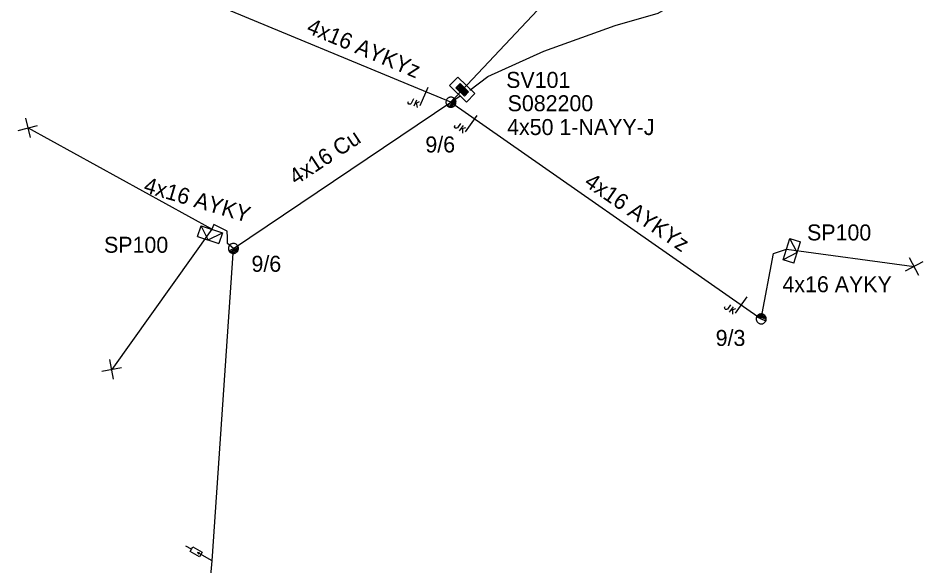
# Model space of a CAD drawing. Extents: x -788458 to -786145, y -1154772 to -1152372.
# Drawn here: x -786965.6 to -786909, y -1154604 to -1154569.7 of the extents above; entities that cross this region are included whole.
import ezdxf

# ---------------------------------------------------------------- set-up
doc = ezdxf.new("R2010")
doc.units = 0
for name, color, linetype in [('Vrstva 1', 7, 'Continuous'), ('Vrstva 12', 7, 'Continuous'), ('Vrstva 13', 7, 'Continuous'), ('Vrstva 15', 7, 'Continuous'), ('Vrstva 16', 7, 'Continuous'), ('Vrstva 18', 7, 'Continuous'), ('Vrstva 2', 7, 'Continuous'), ('Vrstva 28', 7, 'Continuous'), ('Vrstva 29', 7, 'Continuous'), ('Vrstva 30', 7, 'Continuous'), ('Vrstva 31', 7, 'Continuous'), ('Vrstva 33', 7, 'Continuous'), ('Vrstva 34', 7, 'Continuous'), ('Vrstva 5', 7, 'Continuous'), ('Vrstva 52', 7, 'Continuous'), ('Vrstva 54', 7, 'Continuous'), ('Vrstva 55', 7, 'Continuous'), ('Vrstva 59', 7, 'Continuous'), ('Vrstva 6', 7, 'Continuous'), ('Vrstva 8', 7, 'Continuous'), ('Vrstva 9', 7, 'Continuous')]:
    doc.layers.add(name, color=color, linetype=linetype)

# ---------------------------------------------------------------- blocks, each defined once
blk = doc.blocks.new('NN440')
at = {"layer": 'Vrstva 2'}
for points in [[(0.63, 0), (0.63, 0.06), (0.62, 0.13), (0.6, 0.19), (0.58, 0.25), (0.55, 0.31), (0.51, 0.37), (0.47, 0.42), (0.42, 0.46), (0.37, 0.51), (0.32, 0.54), (0.26, 0.57), (0.2, 0.59), (0.13, 0.61), (0.07, 0.62), (0, 0.63), (-0.06, 0.62), (-0.13, 0.61), (-0.19, 0.59), (-0.26, 0.57), (-0.31, 0.54), (-0.37, 0.51), (-0.42, 0.46), (-0.47, 0.42), (-0.51, 0.37), (-0.54, 0.31), (-0.57, 0.25), (-0.6, 0.19), (-0.62, 0.13), (-0.63, 0.06), (-0.63, 0), (-0.63, -0.07), (-0.62, -0.14), (-0.6, -0.2), (-0.57, -0.26), (-0.54, -0.32), (-0.51, -0.37), (-0.47, -0.43), (-0.42, -0.47), (-0.37, -0.51), (-0.31, -0.55), (-0.26, -0.58), (-0.19, -0.6), (-0.13, -0.62), (-0.06, -0.63), (0, -0.63), (0.07, -0.63), (0.13, -0.62), (0.2, -0.6), (0.26, -0.58), (0.32, -0.55), (0.37, -0.51), (0.42, -0.47), (0.47, -0.43), (0.51, -0.37), (0.55, -0.32), (0.58, -0.26), (0.6, -0.2), (0.62, -0.14), (0.63, -0.07), (0.63, 0)], [(-0.63, 0), (0.63, 0)], [(-0.6, -0.18), (0.57, -0.18)], [(-0.51, -0.32), (0.5, -0.32)], [(-0.37, -0.47), (0.35, -0.47)]]:
    blk.add_lwpolyline(points, dxfattribs=at)
blk = doc.blocks.new('NN840')
at = {"layer": 'Vrstva 15'}
for points in [[(0.003, 0.619), (0.003, -0.631)], [(-0.538, -0.385), (-0.538, -0.71)], [(-0.332, -0.385), (-0.332, -0.798)], [(-0.332, -0.641), (-0.125, -0.385)], [(-0.263, -0.557), (-0.091, -0.798)], [(-0.745, -0.71), (-0.745, -0.66)], [(-0.73, -0.764), (-0.745, -0.71)], [(-0.657, -0.798), (-0.73, -0.764)], [(-0.627, -0.798), (-0.657, -0.798)], [(-0.558, -0.764), (-0.627, -0.798)], [(-0.538, -0.71), (-0.558, -0.764)]]:
    blk.add_lwpolyline(points, dxfattribs=at)
blk = doc.blocks.new('NN800')
at = {"layer": 'Vrstva 1'}
for points in [[(-0.442, 0.442), (0.442, -0.442)], [(-0.442, -0.442), (0.442, 0.442)]]:
    blk.add_lwpolyline(points, dxfattribs=at)
blk = doc.blocks.new('NN820')
at = {"layer": 'Vrstva 13'}
for points in [[(-0.003, 0.004), (-0.003, -1.049)], [(-0.165, -0.813), (0.165, -0.813)], [(-0.165, -1.473), (-0.165, -0.813)], [(-0.003, -1.049), (-0.062, -0.926)], [(-0.003, -1.049), (0.057, -0.926)], [(0.165, -0.813), (0.165, -1.473)], [(0.165, -1.473), (-0.165, -1.473)], [(-0.003, -1.473), (-0.003, -1.871)]]:
    blk.add_lwpolyline(points, dxfattribs=at)
blk = doc.blocks.new('NN620')
at = {"layer": 'Vrstva 8'}
for points in [[(0.752, 0.004), (-0.748, 0.004)], [(-0.748, 0.004), (-0.748, -0.746)], [(0.752, -0.746), (0.752, 0.004)], [(0.368, -0.18), (-0.376, -0.18)], [(-0.376, -0.18), (-0.376, -0.558)], [(-0.376, -0.558), (0.368, -0.558)], [(0.321, -0.227), (-0.329, -0.227)], [(-0.329, -0.227), (-0.329, -0.51)], [(-0.329, -0.51), (0.321, -0.51)], [(0.274, -0.274), (-0.281, -0.274)], [(-0.281, -0.274), (-0.281, -0.463)], [(-0.281, -0.463), (0.274, -0.463)], [(0.227, -0.321), (-0.234, -0.321)], [(-0.234, -0.321), (-0.234, -0.416)], [(-0.234, -0.416), (0.227, -0.416)], [(-0.193, -0.369), (0.185, -0.369)], [(0.227, -0.416), (0.227, -0.321)], [(0.274, -0.463), (0.274, -0.274)], [(0.321, -0.51), (0.321, -0.227)], [(0.368, -0.558), (0.368, -0.18)], [(-0.748, -0.746), (0.752, -0.746)]]:
    blk.add_lwpolyline(points, dxfattribs=at)
blk = doc.blocks.new('NN630')
at = {"layer": 'Vrstva 9'}
for points in [[(-0.003, -0.7), (-0.703, 0)], [(-0.703, -0.7), (-0.703, 0), (0.697, 0), (0.697, -0.7)], [(-0.003, -0.7), (0.697, 0)], [(-0.703, -0.7), (0.697, -0.7)]]:
    blk.add_lwpolyline(points, dxfattribs=at)

msp = doc.modelspace()

# ---------------------------------------------------------------- linework, layer by layer
at = {"layer": 'Vrstva 1'}
for points in [[(-786938.55, -1154574.98), (-786925.01, -1154560.56)], [(-786953.694, -1154605.954), (-786953.49, -1154603.668), (-786952.16, -1154584.13), (-786938.55, -1154574.98)]]:
    msp.add_lwpolyline(points, dxfattribs=at)
at = {"layer": 'Vrstva 5'}
for points in [[(-786937.378, -1154574.228), (-786936.24, -1154573.37), (-786932.73, -1154571.78), (-786928.27, -1154570.19), (-786925.58, -1154569.4), (-786924.47, -1154568.76), (-786923.28, -1154567.46), (-786920.52, -1154565.96), (-786919.41, -1154565.46), (-786917.49, -1154564.45), (-786914.82, -1154562.68), (-786913.58, -1154558.8), (-786913.54, -1154557.37), (-786910.93, -1154557.77), (-786910.13, -1154557.99)], [(-786938.55, -1154574.98), (-786937.979, -1154574.587)]]:
    msp.add_lwpolyline(points, dxfattribs=at)
at = {"layer": 'Vrstva 52'}
for points in [[(-786952.16, -1154584.13), (-786952.52, -1154583.82), (-786952.53, -1154583.453), (-786952.54, -1154583.05), (-786953.38, -1154582.63), (-786953.51, -1154582.93)], [(-786919.14, -1154588.54), (-786918.37, -1154584.44), (-786917.56, -1154584.17)]]:
    msp.add_lwpolyline(points, dxfattribs=at)
at = {"layer": 'Vrstva 54'}
for points in [[(-786938.55, -1154574.98), (-786954.96, -1154568.15), (-786954.91, -1154567.81)], [(-786938.55, -1154574.98), (-786919.14, -1154588.54)]]:
    msp.add_lwpolyline(points, dxfattribs=at)
at = {"layer": 'Vrstva 59'}
for points in [[(-786953.51, -1154582.93), (-786965.02, -1154576.59)], [(-786953.51, -1154582.93), (-786959.77, -1154591.7)], [(-786917.56, -1154584.17), (-786909.58, -1154585.26)]]:
    msp.add_lwpolyline(points, dxfattribs=at)

# ---------------------------------------------------------------- block references
at = {"layer": 'Vrstva 13'}
for p, xscale, yscale, rotation in [((-786938.55, -1154574.98), 0.5, 0.5000000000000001, 48.995463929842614), ((-786952.16, -1154584.13), 0.5, 0.5, 28.190275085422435), ((-786919.14, -1154588.54), 0.49999999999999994, 0.5, 155.6707111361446)]:
    msp.add_blockref('NN440', p, dxfattribs=dict(at, xscale=xscale, yscale=yscale, rotation=rotation))
at = {"layer": 'Vrstva 16', "rotation": -119.09316400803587}
msp.add_blockref('NN820', (-786953.49, -1154603.668), dxfattribs=at)
at = {"layer": 'Vrstva 18'}
for p, rotation in [((-786940.254, -1154574.622), -23.45452601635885), ((-786937.297, -1154576.311), -35.43444228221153), ((-786920.408, -1154587.654), -35.43444224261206)]:
    msp.add_blockref('NN840', p, dxfattribs=dict(at, rotation=rotation))
at = {"layer": 'Vrstva 28', "rotation": 136.0531125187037}
msp.add_blockref('NN620', (-786938.103, -1154574.463), dxfattribs=at)
at = {"layer": 'Vrstva 31'}
for p, rotation in [((-786953.51, -1154582.93), -18.08950043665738), ((-786917.56, -1154584.17), 72.34022355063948)]:
    msp.add_blockref('NN630', p, dxfattribs=dict(at, rotation=rotation))
at = {"layer": 'Vrstva 34'}
for p, rotation in [((-786965.02, -1154576.59), -30.81921105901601), ((-786909.58, -1154585.26), 162.92557773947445), ((-786959.77, -1154591.7), 55.55453611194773)]:
    msp.add_blockref('NN800', p, dxfattribs=dict(at, rotation=rotation))

# ---------------------------------------------------------------- texts
at = {"layer": 'Vrstva 12'}
for s, p in [('9/6', (-786940.149, -1154578.123)), ('9/6', (-786951.027, -1154585.59)), ('9/3', (-786921.991, -1154590.229))]:
    msp.add_text(s, height=1, dxfattribs=at).set_placement(p)
at = {"layer": 'Vrstva 2'}
msp.add_text('4x16 Cu', height=1, rotation=33.396, dxfattribs=at).set_placement((-786948.252, -1154580.191))
at = {"layer": 'Vrstva 29'}
msp.add_text('S082200', height=1, dxfattribs=at).set_placement((-786935.005, -1154575.544))
at = {"layer": 'Vrstva 30'}
msp.add_text('SV101', height=1, dxfattribs=at).set_placement((-786935.096, -1154574.084))
at = {"layer": 'Vrstva 33'}
for p in [(-786916.274, -1154583.628), (-786960.25, -1154584.4)]:
    msp.add_text('SP100', height=1, dxfattribs=at).set_placement(p)
at = {"layer": 'Vrstva 54'}
msp.add_text('4x16 AYKY', height=1, rotation=343.61, dxfattribs=at).set_placement((-786957.834, -1154580.595))
msp.add_text('4x16 AYKY', height=1, dxfattribs=at).set_placement((-786917.813, -1154586.869))
at = {"layer": 'Vrstva 55'}
for rotation, p in [(337.277, (-786947.644, -1154570.608)), (325.545, (-786930.277, -1154580.155))]:
    msp.add_text('4x16 AYKYz', height=1, rotation=rotation, dxfattribs=at).set_placement(p)
at = {"layer": 'Vrstva 6'}
msp.add_text('4x50 1-NAYY-J', height=1, dxfattribs=at).set_placement((-786935.035, -1154577.034))

doc.saveas('drawing.dxf')
